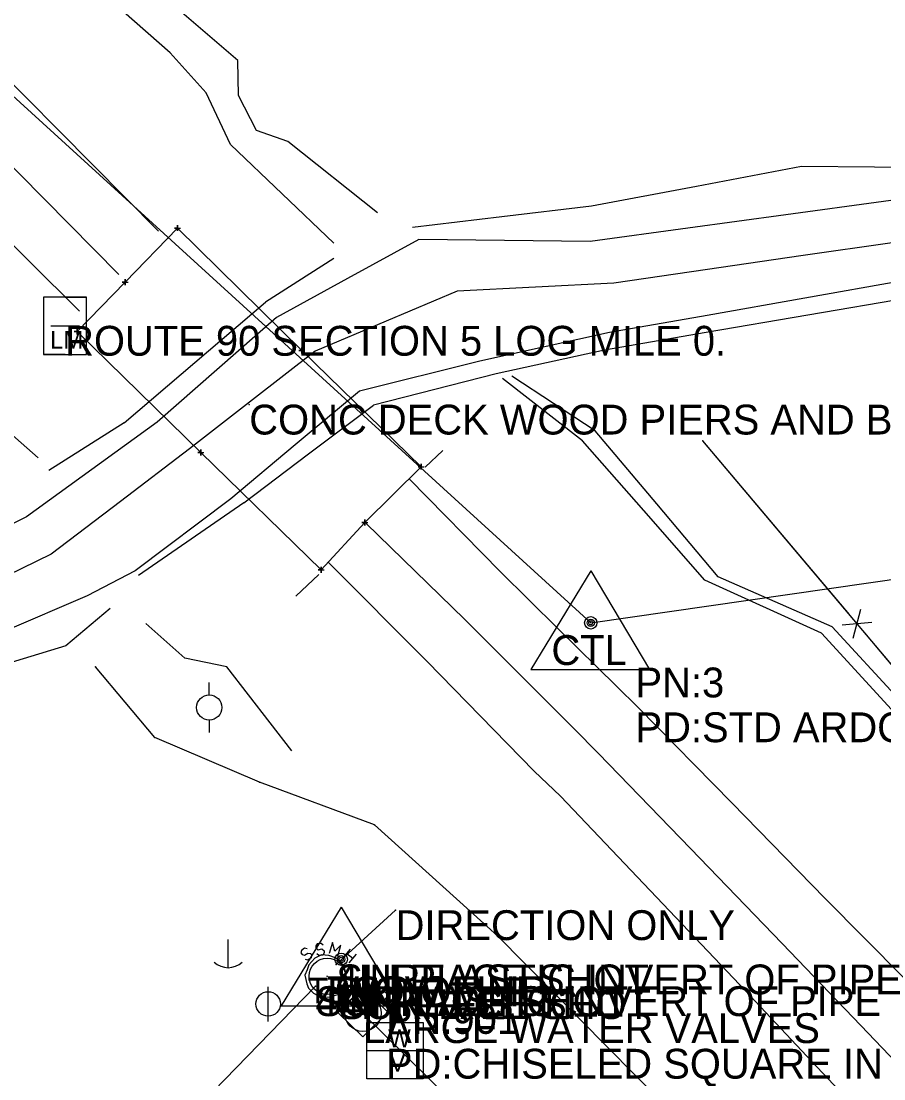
# Model space of a CAD drawing. Extents: x 1660112 to 1662239, y 668919 to 671377.
# Drawn here: x 1661239.8 to 1661384.3, y 670135.7 to 670312.8 of the extents above; entities that cross this region are included whole.
import ezdxf

# ---------------------------------------------------------------- set-up
doc = ezdxf.new("R2010")
doc.units = 0
for name, color, linetype in [('S_BASELINE', 7, 'Continuous'), ('S_BRIDGE', 7, 'Continuous'), ('S_DITCHLINE', 7, 'Continuous'), ('S_EDGE_CONCRETE', 7, 'Continuous'), ('S_EDGE_PAVEMENT', 7, 'Continuous'), ('S_FENCE', 7, 'Continuous'), ('S_GRD_PT_SYM', 7, 'Continuous'), ('S_LOG_MILE', 7, 'Continuous'), ('S_LOG_MILE_ANNOT', 7, 'Continuous'), ('S_MANHOLE_ANNOT', 7, 'Continuous'), ('S_MISC_TOPO_POINT', 7, 'Continuous'), ('S_MSC_PT_SYM', 7, 'Continuous'), ('S_PAVEMENT_CROWN', 7, 'Continuous'), ('S_PRIMARY_CTL', 7, 'Continuous'), ('S_PRIMARY_CTL_ANNOT', 7, 'Continuous'), ('S_SANITARY_SEWER', 7, 'Continuous'), ('S_SANITARY_SEWER_ANNOT', 7, 'Continuous'), ('S_STR_PT_SYM', 7, 'Continuous'), ('S_STREAM', 7, 'Continuous'), ('S_SURVEY_TEXT_ANNOT', 7, 'Continuous'), ('S_UTILITY_POLE', 7, 'Continuous'), ('S_UTL_PT_SYM', 7, 'Continuous'), ('S_WALL', 7, 'Continuous'), ('S_WATER_UTILITIES', 7, 'Continuous')]:
    doc.layers.add(name, color=color, linetype=linetype)

msp = doc.modelspace()

# ---------------------------------------------------------------- linework, layer by layer
at = {"layer": 'S_BASELINE'}
for p, q in [((1660813.76, 670687.35), (1661335.19, 670212.07)), ((1661335.19, 670212.07), (1662115.18, 670324.54))]:
    msp.add_line(p, q, dxfattribs=at)
at = {"layer": 'S_BRIDGE'}
for p, q in [((1661257.22, 670269.12), (1661265.95, 670278.2)), ((1661265.95, 670278.2), (1661286.82, 670257.7)), ((1661249.15, 670260.87), (1661257.22, 670269.12)), ((1661269.88, 670240.62), (1661249.15, 670260.87)), ((1661286.82, 670257.7), (1661306.8, 670238.22)), ((1661290.03, 670220.95), (1661269.88, 670240.62)), ((1661306.8, 670238.22), (1661297.35, 670228.87)), ((1661297.35, 670228.87), (1661290.03, 670220.95))]:
    msp.add_line(p, q, dxfattribs=at)
at = {"layer": 'S_DITCHLINE'}
for points in [[(1661299.45, 670280.74), (1661284.47, 670292.7), (1661279.2, 670294.55), (1661276.17, 670300.4), (1661276.07, 670306.25), (1661258.9, 670321.05), (1661241.72, 670335.84), (1661231.17, 670346.95), (1661220.61, 670358.06), (1661210.06, 670369.17), (1661199.5, 670380.28), (1661190.45, 670390.39), (1661181.41, 670400.5), (1661172.36, 670410.61), (1661163.31, 670420.71), (1661149.32, 670433.4), (1661135.33, 670446.1), (1661121.34, 670458.79), (1661107.35, 670471.48)], [(1661292.16, 670275.66), (1661274.83, 670292.21), (1661270.79, 670300.84), (1661264.75, 670307.54), (1661250.97, 670319.7), (1661237.18, 670331.85), (1661227.07, 670342.64), (1661216.95, 670353.42), (1661206.84, 670364.21), (1661196.72, 670375), (1661186.88, 670384.5), (1661177.03, 670394.01), (1661167.19, 670403.51), (1661157.34, 670413.01), (1661144.39, 670427.16), (1661131.45, 670441.31), (1661118.5, 670455.46), (1661105.55, 670469.61)], [(1661242.65, 670239.7), (1661224.03, 670256.09), (1661205.42, 670272.49), (1661195.13, 670280.52), (1661184.84, 670288.55), (1661175.36, 670299.38), (1661165.88, 670310.21), (1661156.4, 670321.03), (1661146.92, 670331.86), (1661137.55, 670341.19), (1661128.17, 670350.53), (1661118.79, 670359.86), (1661109.42, 670369.2), (1661097.31, 670380.98), (1661085.2, 670392.76), (1661068.34, 670408.15)], [(1661495.46, 670073.89), (1661482.85, 670088.25), (1661470.25, 670102.6), (1661470.41, 670103.23), (1661460.8, 670115.6), (1661451.19, 670127.97), (1661437.9, 670142.65), (1661424.62, 670157.34), (1661411.2, 670172.34), (1661397.77, 670187.35), (1661386.72, 670199.36), (1661375.66, 670211.37), (1661356.56, 670219.75), (1661346.24, 670231.99), (1661335.91, 670244.22), (1661322, 670253.4)], [(1661494.51, 670072.98), (1661481.63, 670087.01), (1661468.75, 670101.04), (1661468.56, 670102.05), (1661459.49, 670114.59), (1661450.42, 670127.12), (1661437.16, 670141.71), (1661423.9, 670156.29), (1661409.97, 670171.2), (1661396.04, 670186.11), (1661384.96, 670198.23), (1661373.87, 670210.36), (1661354.32, 670219.23), (1661344.06, 670230.9), (1661333.8, 670242.57), (1661320.4, 670253.01)], [(1661285.14, 670190.64), (1661274.25, 670204.7), (1661267.2, 670206.15), (1661260.68, 670211.95)]]:
    msp.add_lwpolyline(points, dxfattribs=at)
at = {"layer": 'S_EDGE_CONCRETE'}
msp.add_lwpolyline([(1661293, 670149.81), (1661293.5, 670150.75), (1661294.22, 670151.81), (1661294.22, 670153.16), (1661293.96, 670154.35), (1661293.3, 670155.31), (1661292.45, 670155.96), (1661291.31, 670156.34), (1661290.11, 670156.43), (1661288.99, 670155.89), (1661287.99, 670154.78), (1661287.69, 670153.93), (1661287.29, 670153.06), (1661287.65, 670151.62), (1661287.94, 670150.85), (1661288.74, 670150.02), (1661289.46, 670149.65), (1661290.67, 670149.36), (1661291.56, 670149.44), (1661293.01, 670149.87)], dxfattribs=at)
msp.add_lwpolyline([(1661292.81, 670146.81), (1661297, 670142.7), (1661301.21, 670146.85), (1661297.06, 670151.06)], close=True, dxfattribs=at)
at = {"layer": 'S_EDGE_PAVEMENT'}
for points in [[(1661249.53, 670264.29), (1661232.81, 670280.83), (1661216.09, 670297.37), (1661206.48, 670306.91), (1661196.87, 670316.45), (1661187.26, 670325.99), (1661177.65, 670335.53), (1661168.35, 670344.75), (1661159.06, 670353.98), (1661149.76, 670363.2), (1661140.47, 670372.43), (1661130.68, 670382.11), (1661120.89, 670391.8), (1661111.1, 670401.49), (1661101.31, 670411.17)], [(1661262.8, 670277.66), (1661246.17, 670294.45), (1661229.53, 670311.23), (1661220, 670320.86), (1661210.47, 670330.49), (1661200.95, 670340.13), (1661191.42, 670349.76), (1661181.92, 670359.12), (1661172.42, 670368.49), (1661162.93, 670377.85), (1661153.43, 670387.22), (1661143.78, 670396.82), (1661134.14, 670406.42)], [(1661528.89, 670006.64), (1661525.81, 670010.93), (1661521.19, 670007.06), (1661512.12, 670017.42), (1661503.06, 670027.78), (1661494.14, 670038.45), (1661485.22, 670049.12), (1661475.65, 670058.13), (1661469.7, 670064.69), (1661453.26, 670082.63), (1661441.58, 670095.54), (1661429.9, 670108.45), (1661415.33, 670123.89), (1661400.76, 670139.32), (1661387.62, 670152.61), (1661374.47, 670165.9), (1661358.81, 670181.9), (1661343.14, 670197.9), (1661339.48, 670201.44), (1661329.75, 670211.05), (1661320.02, 670220.65), (1661304.77, 670236.19)], [(1661507.57, 669985.17), (1661503.63, 669990.55), (1661503.83, 669996.41), (1661492.59, 670008.33), (1661484.98, 670015.56), (1661475.91, 670025.37), (1661466.84, 670035.18), (1661454.4, 670049.73), (1661445.95, 670059), (1661437.51, 670068.28), (1661425.39, 670081.13), (1661413.28, 670093.99), (1661399.68, 670108.94), (1661386.08, 670123.89), (1661373.13, 670137.66), (1661360.18, 670151.43), (1661345.14, 670167.24), (1661330.11, 670183.04), (1661325.69, 670187.24), (1661316.74, 670196.41), (1661307.8, 670205.57), (1661291.28, 670222.16)]]:
    msp.add_lwpolyline(points, dxfattribs=at)
at = {"layer": 'S_FENCE'}
for p, q in [((1661437.44, 670143.55), (1661353.95, 670242.57)), ((1661379.15, 670209.5), (1661380.44, 670214.33)), ((1661379.15, 670209.5), (1661380.44, 670214.33)), ((1661382.28, 670212.14), (1661377.3, 670211.69)), ((1661382.28, 670212.14), (1661377.3, 670211.69))]:
    msp.add_line(p, q, dxfattribs=at)
for points in [[(1661378.51, 670213.45), (1661353.95, 670242.57)], [(1661378.51, 670213.45), (1661353.95, 670242.57)], [(1661393.97, 670195.1), (1661381.08, 670210.39)], [(1661393.97, 670195.1), (1661381.08, 670210.39)]]:
    msp.add_lwpolyline(points, dxfattribs=at)
at = {"layer": 'S_GRD_PT_SYM'}
for points in [[(1661292.56, 670154.83), (1661292.56, 670154.88), (1661292.56, 670154.83), (1661292.51, 670154.83), (1661292.56, 670154.83), (1661292.56, 670154.78), (1661292.56, 670154.83), (1661292.61, 670154.83)], [(1661289.08, 670151.19), (1661289.08, 670151.24), (1661289.08, 670151.19), (1661289.03, 670151.19), (1661289.08, 670151.19), (1661289.08, 670151.14), (1661289.08, 670151.19), (1661289.13, 670151.19)], [(1661292.91, 670150.69), (1661292.91, 670150.74), (1661292.91, 670150.69), (1661292.86, 670150.69), (1661292.91, 670150.69), (1661292.91, 670150.64), (1661292.91, 670150.69), (1661292.96, 670150.69)]]:
    msp.add_lwpolyline(points, dxfattribs=at)
at = {"layer": 'S_LOG_MILE'}
for p, q in [((1661247.15, 670266.61), (1661250.75, 670266.61)), ((1661244.75, 670261.81), (1661249.55, 670261.81)), ((1661247.15, 670257.01), (1661243.55, 670257.01))]:
    msp.add_line(p, q, dxfattribs=at)
msp.add_lwpolyline([(1661250.75, 670266.61), (1661243.55, 670266.61), (1661243.55, 670257.01), (1661250.75, 670257.01)], close=True, dxfattribs=at)
at = {"layer": 'S_MSC_PT_SYM'}
for points in [[(1661277.99, 670248.61), (1661277.99, 670248.66), (1661277.99, 670248.61), (1661277.94, 670248.61), (1661277.99, 670248.61), (1661277.99, 670248.56), (1661277.99, 670248.61), (1661278.04, 670248.61)], [(1661353.95, 670242.57), (1661353.95, 670242.62), (1661353.95, 670242.57), (1661353.9, 670242.57), (1661353.95, 670242.57), (1661353.95, 670242.52), (1661353.95, 670242.57), (1661354, 670242.57)]]:
    msp.add_lwpolyline(points, dxfattribs=at)
at = {"layer": 'S_PAVEMENT_CROWN'}
for points in [[(1661256.17, 670270.41), (1661239.48, 670287.26), (1661222.79, 670304.1), (1661213.05, 670313.75), (1661203.32, 670323.4), (1661193.59, 670333.05), (1661183.85, 670342.7), (1661174.57, 670351.81), (1661165.29, 670360.92), (1661156.01, 670370.03), (1661146.73, 670379.14), (1661137.08, 670388.79), (1661127.43, 670398.43), (1661117.78, 670408.07)], [(1661518.06, 669996.03), (1661505.4, 670009.31), (1661492.74, 670022.59), (1661480.19, 670036.99), (1661467.64, 670051.39), (1661473.76, 670044.39), (1661461.34, 670057.98), (1661445.4, 670075.38), (1661443.99, 670076.39), (1661432.69, 670088.65), (1661421.39, 670100.9), (1661407.48, 670115.88), (1661393.57, 670130.85), (1661380.41, 670144.59), (1661367.25, 670158.33), (1661351.88, 670174.26), (1661336.51, 670190.18), (1661332.38, 670194.36), (1661323.21, 670203.51), (1661314.05, 670212.66), (1661297.56, 670228.68)]]:
    msp.add_lwpolyline(points, dxfattribs=at)
at = {"layer": 'S_PRIMARY_CTL'}
for p, q in [((1661335.19, 670220.77), (1661325.16, 670204.26)), ((1661335.19, 670220.77), (1661345.02, 670204.26)), ((1661325.16, 670204.26), (1661345.02, 670204.26)), ((1661293.39, 670164.41), (1661283.35, 670147.9)), ((1661293.39, 670164.41), (1661303.21, 670147.9)), ((1661283.35, 670147.9), (1661303.21, 670147.9))]:
    msp.add_line(p, q, dxfattribs=at)
for centre, radius in [((1661335.19, 670212.07), 1.04), ((1661335.19, 670212.07), 0.609), ((1661335.19, 670212.07), 0.344), ((1661293.39, 670155.71), 1.04), ((1661293.39, 670155.71), 0.609), ((1661293.39, 670155.71), 0.344)]:
    msp.add_circle(centre, radius, dxfattribs=at)
at = {"layer": 'S_SANITARY_SEWER'}
for p, q in [((1661292.56, 670154.83), (1661302.51, 670163.92)), ((1661287.27, 670157.55), (1661286.73, 670157.16)), ((1661287.69, 670157.47), (1661287.27, 670157.55)), ((1661286.73, 670157.16), (1661286.65, 670156.77)), ((1661286.65, 670156.77), (1661286.84, 670156.5)), ((1661286.84, 670156.5), (1661287.27, 670156.38)), ((1661287.27, 670156.38), (1661287.81, 670156.73)), ((1661287.81, 670156.73), (1661288.28, 670156.65)), ((1661288.35, 670155.96), (1661287.81, 670155.57)), ((1661288.28, 670156.65), (1661288.43, 670156.38)), ((1661288.43, 670156.38), (1661288.35, 670155.96)), ((1661293.7, 670155.92), (1661294.94, 670157.39)), ((1661294.36, 670156.69), (1661295.33, 670155.88)), ((1661295.91, 670156.58), (1661294.67, 670155.1)), ((1661287.81, 670155.57), (1661287.42, 670155.65)), ((1661289.08, 670151.19), (1660996.93, 669850.58)), ((1661292.72, 670150.97), (1661292.64, 670150.59)), ((1661292.64, 670150.59), (1661292.83, 670150.31)), ((1661293.26, 670151.36), (1661292.72, 670150.97)), ((1661704.02, 669745.54), (1661292.91, 670150.69)), ((1661293.69, 670151.28), (1661293.26, 670151.36)), ((1661293.26, 670150.2), (1661293.8, 670150.55)), ((1661293.8, 670150.55), (1661294.27, 670150.47)), ((1661294.27, 670150.47), (1661294.42, 670150.2)), ((1661299.69, 670149.73), (1661300.93, 670151.21)), ((1661300.35, 670150.51), (1661301.32, 670149.69)), ((1661292.83, 670150.31), (1661293.26, 670150.2)), ((1661293.8, 670149.38), (1661293.41, 670149.46)), ((1661294.34, 670149.77), (1661293.8, 670149.38)), ((1661294.42, 670150.2), (1661294.34, 670149.77)), ((1661301.9, 670150.39), (1661300.66, 670148.92))]:
    msp.add_line(p, q, dxfattribs=at)
for points in [[(1661290.37, 670158.09), (1661290.02, 670158.36), (1661289.36, 670158.28), (1661289.13, 670157.93), (1661289.17, 670157.62), (1661289.52, 670157.31), (1661290.14, 670157.43), (1661290.52, 670157.12), (1661290.56, 670156.81), (1661290.29, 670156.42), (1661289.67, 670156.34), (1661289.32, 670156.62)], [(1661292.81, 670156.23), (1661293.35, 670158.09), (1661292.31, 670157.08), (1661291.92, 670158.51), (1661291.38, 670156.65)], [(1661298.8, 670150.04), (1661299.34, 670151.9), (1661298.3, 670150.9), (1661297.91, 670152.33), (1661297.37, 670150.47)], [(1661296.36, 670151.9), (1661296.01, 670152.17), (1661295.35, 670152.1), (1661295.12, 670151.75), (1661295.16, 670151.44), (1661295.51, 670151.13), (1661296.13, 670151.24), (1661296.51, 670150.93), (1661296.55, 670150.62), (1661296.28, 670150.24), (1661295.66, 670150.16), (1661295.31, 670150.43)]]:
    msp.add_lwpolyline(points, dxfattribs=at)
for centre in [(1661291.05, 670152.85), (1661297.04, 670146.67)]:
    msp.add_circle(centre, 3.05, dxfattribs=at)
at = {"layer": 'S_STR_PT_SYM'}
for points in [[(1661265.95, 670278.2), (1661265.95, 670278.7), (1661265.95, 670278.2), (1661265.45, 670278.2), (1661265.95, 670278.2), (1661265.95, 670277.7), (1661265.95, 670278.2), (1661266.45, 670278.2)], [(1661257.22, 670269.12), (1661257.22, 670269.62), (1661257.22, 670269.12), (1661256.72, 670269.12), (1661257.22, 670269.12), (1661257.22, 670268.62), (1661257.22, 670269.12), (1661257.72, 670269.12)], [(1661249.15, 670260.87), (1661249.15, 670261.37), (1661249.15, 670260.87), (1661248.65, 670260.87), (1661249.15, 670260.87), (1661249.15, 670260.37), (1661249.15, 670260.87), (1661249.65, 670260.87)], [(1661286.82, 670257.7), (1661286.82, 670258.2), (1661286.82, 670257.7), (1661286.32, 670257.7), (1661286.82, 670257.7), (1661286.82, 670257.2), (1661286.82, 670257.7), (1661287.32, 670257.7)], [(1661269.88, 670240.62), (1661269.88, 670241.12), (1661269.88, 670240.62), (1661269.38, 670240.62), (1661269.88, 670240.62), (1661269.88, 670240.12), (1661269.88, 670240.62), (1661270.38, 670240.62)], [(1661306.8, 670238.22), (1661306.8, 670238.72), (1661306.8, 670238.22), (1661306.3, 670238.22), (1661306.8, 670238.22), (1661306.8, 670237.72), (1661306.8, 670238.22), (1661307.3, 670238.22)], [(1661297.35, 670228.87), (1661297.35, 670229.37), (1661297.35, 670228.87), (1661296.85, 670228.87), (1661297.35, 670228.87), (1661297.35, 670228.37), (1661297.35, 670228.87), (1661297.85, 670228.87)], [(1661290.03, 670220.95), (1661290.03, 670221.45), (1661290.03, 670220.95), (1661289.53, 670220.95), (1661290.03, 670220.95), (1661290.03, 670220.45), (1661290.03, 670220.95), (1661290.53, 670220.95)]]:
    msp.add_lwpolyline(points, dxfattribs=at)
at = {"layer": 'S_STREAM'}
for points in [[(1661620.34, 670335.21), (1661597.17, 670329.75), (1661574, 670324.29), (1661550.82, 670318.83), (1661527.65, 670313.37), (1661513.53, 670311.73), (1661499.41, 670310.09), (1661492.64, 670311.04), (1661490.16, 670306.19), (1661483.49, 670303.19), (1661469.16, 670295.94), (1661446.28, 670293.35), (1661423.4, 670290.75), (1661409.17, 670289.53), (1661394.93, 670288.3), (1661370.48, 670288.49), (1661352.9, 670285.18), (1661335.31, 670281.88), (1661320.32, 670280.07), (1661305.33, 670278.26)], [(1661622.8, 670312.05), (1661599.9, 670307.69), (1661577, 670303.33), (1661554.1, 670298.98), (1661531.19, 670294.62), (1661517.62, 670291.37), (1661504.05, 670288.12), (1661490.48, 670284.87), (1661476.91, 670281.62), (1661458.63, 670279.27), (1661440.34, 670276.92), (1661422.06, 670274.57), (1661403.77, 670272.22), (1661387.42, 670269.33), (1661371.06, 670266.44), (1661354.71, 670263.56), (1661338.35, 670260.67), (1661316.6, 670255.88), (1661296.46, 670250.86), (1661285.68, 670241.86), (1661274.9, 670232.86), (1661258.9, 670220.78), (1661250.84, 670216.6), (1661237.04, 670210.68)], [(1661623.56, 670311.06), (1661600.76, 670306.67), (1661577.96, 670302.29), (1661555.16, 670297.9), (1661532.36, 670293.52), (1661508.21, 670288.49), (1661492.78, 670284.3), (1661477.36, 670280.12), (1661459.42, 670277.44), (1661441.48, 670274.76), (1661423.55, 670272.09), (1661405.61, 670269.41), (1661388.57, 670266.5), (1661371.54, 670263.59), (1661354.51, 670260.67), (1661337.47, 670257.76), (1661319.37, 670253.79), (1661298.79, 670248.53)], [(1661498.85, 670303.49), (1661484.15, 670299.37), (1661469.46, 670295.26), (1661452.24, 670292.66), (1661435.03, 670290.06), (1661417.81, 670287.47), (1661400.59, 670284.87), (1661384.22, 670282.64), (1661367.85, 670280.4), (1661351.48, 670278.17), (1661335.11, 670275.93), (1661320.77, 670276.1), (1661306.42, 670276.27), (1661294.47, 670269.73), (1661282.53, 670263.19), (1661272.56, 670254.42), (1661262.59, 670245.66), (1661251.64, 670237.74), (1661240.7, 670229.82), (1661218.36, 670218.7)], [(1661502.1, 670294.89), (1661488.35, 670290.94), (1661474.61, 670287), (1661456.4, 670284.77), (1661438.18, 670282.53), (1661419.96, 670280.3), (1661401.75, 670278.07), (1661386.08, 670275.8), (1661370.4, 670273.52), (1661354.73, 670271.25), (1661339.06, 670268.97), (1661325.94, 670268.28), (1661312.82, 670267.6), (1661300.92, 670262.59), (1661289.01, 670257.59), (1661278.51, 670249.41), (1661268, 670241.23), (1661256.41, 670232.4), (1661244.82, 670223.57), (1661232.52, 670217.57)], [(1661292.14, 670273.1), (1661280.7, 670265.75)], [(1661257.02, 670245.54), (1661268.86, 670255.65), (1661280.7, 670265.75)], [(1661277.08, 670232.16), (1661287.93, 670240.35), (1661298.79, 670248.53)], [(1661257.02, 670245.54), (1661244.41, 670237.57)], [(1661277.08, 670232.16), (1661259.42, 670219.97)], [(1661254.7, 670214.48), (1661247.25, 670208.21), (1661225.75, 670201.67), (1661211.58, 670201.81), (1661197.41, 670201.96), (1661183.24, 670202.1), (1661169.07, 670202.24), (1661154.61, 670206.46), (1661140.15, 670210.67), (1661126.98, 670218.08), (1661113.36, 670211.62), (1661104.67, 670201.88), (1661095.98, 670192.14), (1661082.19, 670186.21), (1661068.4, 670180.28), (1661054.61, 670174.34), (1661040.82, 670168.41), (1661022.25, 670157.95), (1661011.73, 670139.15), (1661001.22, 670120.35)]]:
    msp.add_lwpolyline(points, dxfattribs=at)
at = {"layer": 'S_UTILITY_POLE'}
for p, q in [((1661271.27, 670199.96), (1661271.27, 670202.09)), ((1661271.27, 670195.74), (1661271.27, 670193.69)), ((1661274.4, 670159.02), (1661274.4, 670154.29)), ((1661281.16, 670145.3), (1661281.16, 670151.09))]:
    msp.add_line(p, q, dxfattribs=at)
for centre, radius in [((1661271.29, 670197.88), 2.11), ((1661281.16, 670148.23), 2.05)]:
    msp.add_circle(centre, radius, dxfattribs=at)
msp.add_arc((1661274.46, 670157.71), 3.41, 226.3972, 313.6028, dxfattribs=at)
at = {"layer": 'S_UTL_PT_SYM'}
for points in [[(1661252.22, 670204.72), (1661252.22, 670204.77), (1661252.22, 670204.72), (1661252.17, 670204.72), (1661252.22, 670204.72), (1661252.22, 670204.67), (1661252.22, 670204.72), (1661252.27, 670204.72)], [(1661262.17, 670192.84), (1661262.17, 670192.89), (1661262.17, 670192.84), (1661262.12, 670192.84), (1661262.17, 670192.84), (1661262.17, 670192.79), (1661262.17, 670192.84), (1661262.22, 670192.84)], [(1661279.71, 670185.37), (1661279.71, 670185.42), (1661279.71, 670185.37), (1661279.66, 670185.37), (1661279.71, 670185.37), (1661279.71, 670185.32), (1661279.71, 670185.37), (1661279.76, 670185.37)], [(1661298.96, 670178.23), (1661298.96, 670178.28), (1661298.96, 670178.23), (1661298.91, 670178.23), (1661298.96, 670178.23), (1661298.96, 670178.18), (1661298.96, 670178.23), (1661299.01, 670178.23)], [(1661302.51, 670163.92), (1661302.51, 670163.97), (1661302.51, 670163.92), (1661302.45, 670163.92), (1661302.51, 670163.92), (1661302.51, 670163.87), (1661302.51, 670163.92), (1661302.55, 670163.92)], [(1661319.59, 670159.62), (1661319.59, 670159.67), (1661319.59, 670159.62), (1661319.54, 670159.62), (1661319.59, 670159.62), (1661319.59, 670159.57), (1661319.59, 670159.62), (1661319.64, 670159.62)], [(1661292.56, 670154.83), (1661292.56, 670154.88), (1661292.56, 670154.83), (1661292.51, 670154.83), (1661292.56, 670154.83), (1661292.56, 670154.78), (1661292.56, 670154.83), (1661292.61, 670154.83)], [(1661291.05, 670152.85), (1661291.05, 670152.9), (1661291.05, 670152.85), (1661291, 670152.85), (1661291.05, 670152.85), (1661291.05, 670152.8), (1661291.05, 670152.85), (1661291.1, 670152.85)], [(1661289.08, 670151.19), (1661289.08, 670151.24), (1661289.08, 670151.19), (1661289.03, 670151.19), (1661289.08, 670151.19), (1661289.08, 670151.14), (1661289.08, 670151.19), (1661289.13, 670151.19)], [(1661292.91, 670150.69), (1661292.91, 670150.74), (1661292.91, 670150.69), (1661292.86, 670150.69), (1661292.91, 670150.69), (1661292.91, 670150.64), (1661292.91, 670150.69), (1661292.96, 670150.69)]]:
    msp.add_lwpolyline(points, dxfattribs=at)
at = {"layer": 'S_WALL'}
for points in [[(1661310.4, 670240.92), (1661307.47, 670238.13)], [(1661285.79, 670216.52), (1661289.62, 670220.15)]]:
    msp.add_lwpolyline(points, dxfattribs=at)
at = {"layer": 'S_WATER_UTILITIES'}
for p, q in [((1661262.17, 670192.84), (1661252.22, 670204.72)), ((1661279.71, 670185.37), (1661262.17, 670192.84)), ((1661298.96, 670178.23), (1661279.71, 670185.37)), ((1661319.59, 670159.62), (1661298.96, 670178.23)), ((1661357.16, 670121.64), (1661319.59, 670159.62)), ((1661297.71, 670145.12), (1661307.13, 670145.12)), ((1661297.71, 670135.7), (1661297.71, 670145.12)), ((1661307.13, 670145.12), (1661307.13, 670135.7)), ((1661297.71, 670140.43), (1661307.13, 670140.43)), ((1661307.13, 670135.7), (1661297.71, 670135.7))]:
    msp.add_line(p, q, dxfattribs=at)

# ---------------------------------------------------------------- texts
at = {"layer": 'S_LOG_MILE'}
msp.add_text('LM', height=3, rotation=360, dxfattribs=at).set_placement((1661244.61, 670257.97))
at = {"layer": 'S_LOG_MILE_ANNOT'}
msp.add_text('ROUTE 90 SECTION 5 LOG MILE 0.', height=5, dxfattribs=at).set_placement((1661247.15, 670256.81))
at = {"layer": 'S_MANHOLE_ANNOT'}
for s, p in [('FLOW LINE', (1661291.05, 670147.85)), ('LARGE WATER VALVES', (1661297.04, 670141.67))]:
    msp.add_text(s, height=5, dxfattribs=at).set_placement(p)
at = {"layer": 'S_MISC_TOPO_POINT'}
for p in [(1661292.56, 670149.83), (1661289.08, 670146.19), (1661292.91, 670145.69)]:
    msp.add_text('SURFACE SHOT', height=5, dxfattribs=at).set_placement(p)
at = {"layer": 'S_PRIMARY_CTL'}
for s, height, p in [('CTL', 5, (1661328.6, 670205)), ('TBM', 4.287, (1661287.74, 670148.32))]:
    msp.add_text(s, height=height, rotation=360, dxfattribs=at).set_placement(p)
at = {"layer": 'S_PRIMARY_CTL_ANNOT'}
for s, p in [('PN:3', (1661342.69, 670199.57)), ('PD:STD ARDOT CAP STAMPED PN:3', (1661342.69, 670192.07)), ('PN:901', (1661300.89, 670143.21)), ('PD:CHISELED SQUARE IN CONC', (1661300.89, 670135.71))]:
    msp.add_text(s, height=5, dxfattribs=at).set_placement(p)
at = {"layer": 'S_SANITARY_SEWER_ANNOT'}
for s, p in [('DIRECTION ONLY', (1661302.51, 670158.92)), ('4IN PLASTIC INVERT OF PIPE', (1661292.56, 670149.83)), ('TOP OF LID', (1661291.05, 670147.85)), ('4IN PLASTIC INVERT OF PIPE', (1661289.08, 670146.19)), ('4IN PLASTIC', (1661292.91, 670145.69))]:
    msp.add_text(s, height=5, dxfattribs=at).set_placement(p)
at = {"layer": 'S_SURVEY_TEXT_ANNOT'}
msp.add_text('CONC DECK WOOD PIERS AND BEAMS', height=5, dxfattribs=at).set_placement((1661277.99, 670243.61))
at = {"layer": 'S_WATER_UTILITIES'}
for s, p in [('W', (1661301.26, 670140.96)), ('V', (1661301.5, 670136.9))]:
    msp.add_text(s, height=3, rotation=360, dxfattribs=at).set_placement(p)

doc.saveas('drawing.dxf')
